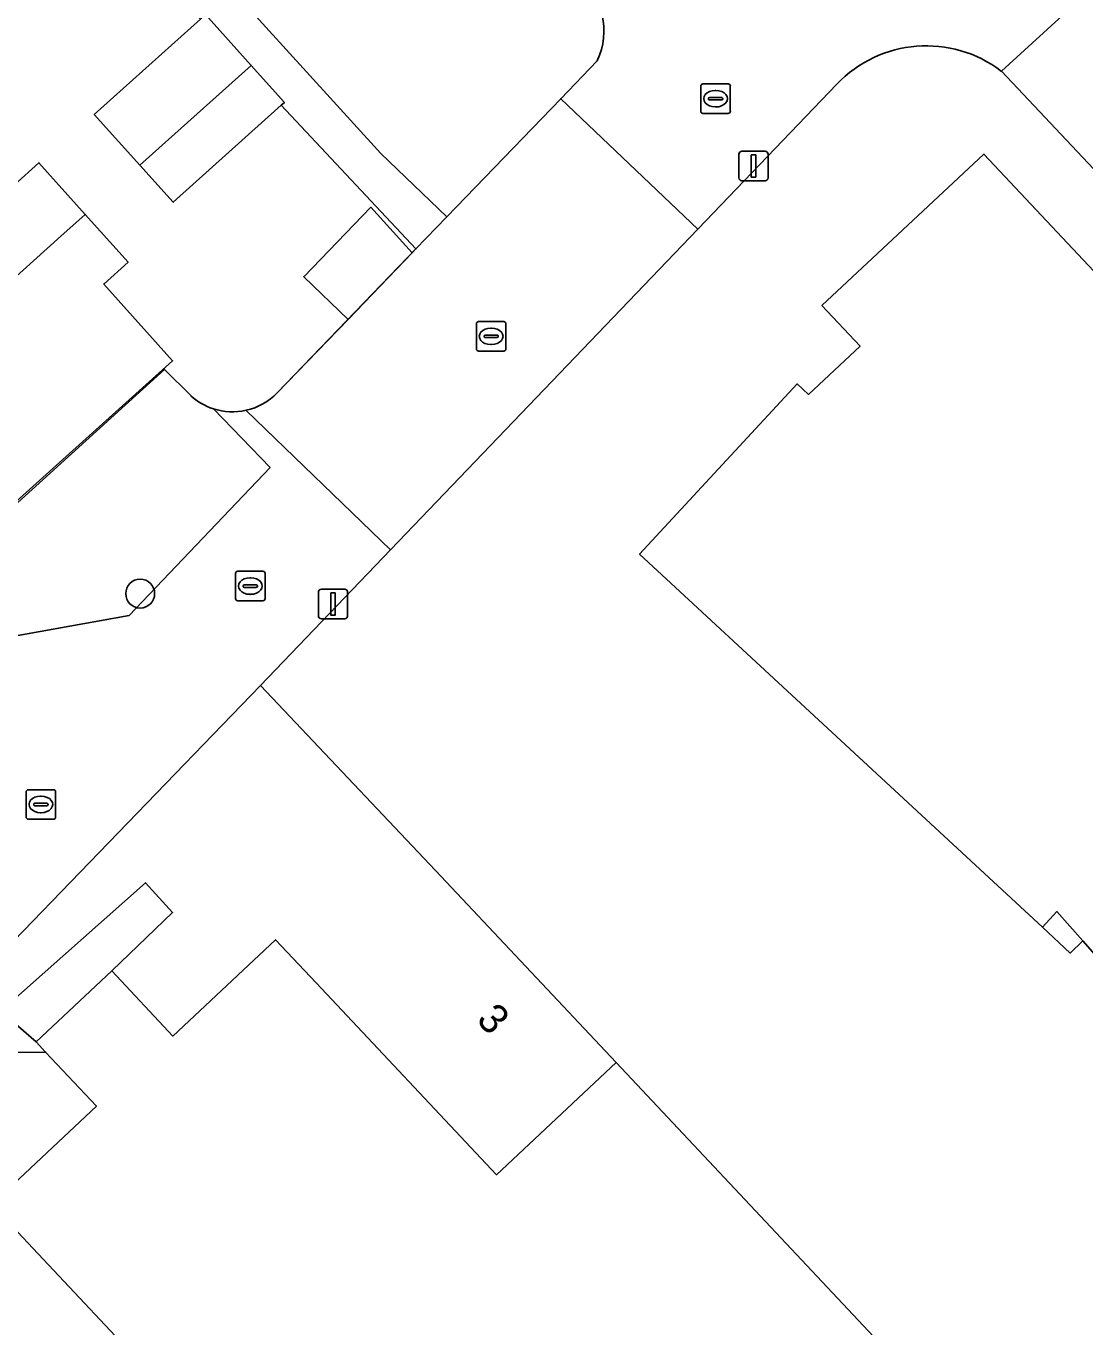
# Model space of a CAD drawing. Extents: x 162344 to 162869, y 381217 to 381818.
# Drawn here: x 162687 to 162722.83, y 381421.83 to 381465.85 of the extents above; entities that cross this region are included whole.
import ezdxf

# ---------------------------------------------------------------- set-up
doc = ezdxf.new("R2010")
doc.units = 0
for name, color, linetype in [('IMGEO_Boom', 7, 'Continuous'), ('IMGEO_Erf', 7, 'Continuous'), ('IMGEO_Kolk', 7, 'Continuous'), ('IMGEO_Lichtmast', 7, 'Continuous'), ('IMGEO_Muur', 7, 'Continuous'), ('IMGEO_Pand', 7, 'Continuous'), ('IMGEO_Pand_nummerreeks', 7, 'Continuous'), ('IMGEO_Pand_overbouw', 7, 'Continuous'), ('IMGEO_Rijbaan_lokaal_open', 7, 'Continuous'), ('IMGEO_Terreindeel_open', 7, 'Continuous'), ('IMGEO_Voetpad_open', 7, 'Continuous')]:
    doc.layers.add(name, color=color, linetype=linetype)

msp = doc.modelspace()

# ---------------------------------------------------------------- linework, layer by layer
at = {"layer": 'IMGEO_Boom'}
msp.add_circle((162690.863, 381446.627), 0.489, dxfattribs=at)
at = {"layer": 'IMGEO_Erf'}
for points in [[(162685.58, 381476.325), (162688.135, 381473.509), (162691.814, 381476.884), (162693.17, 381475.405), (162694.585, 381473.863), (162690.89, 381470.473), (162699.002, 381461.533), (162701.237, 381459.381), (162705.092, 381463.385), (162706.33, 381464.671)], [(162695.638, 381463.162), (162691.98, 381459.878), (162690.856, 381461.131), (162689.308, 381462.855), (162692.902, 381466.082), (162688.04, 381471.271), (162684.241, 381467.846)], [(162754.013, 381428.168), (162752.967, 381429.308), (162720.009, 381464.312)], [(162714.432, 381463.872), (162709.731, 381458.964), (162699.33, 381448.107), (162694.93, 381443.515), (162700.859, 381437.25), (162706.964, 381430.752), (162720.044, 381416.828), (162715.93, 381412.961), (162723.279, 381405.142), (162719.898, 381401.952), (162721.872, 381399.698), (162719.263, 381397.26), (162717.216, 381399.452), (162713.77, 381396.149), (162709.224, 381401.003), (162706.22, 381398.189), (162703.408, 381401.193), (162687.52, 381386.257), (162689.397, 381384.258)], [(162695.501, 381453.423), (162697.897, 381455.912), (162696.398, 381457.355), (162698.666, 381459.711), (162700.069, 381458.168), (162700.195, 381458.299), (162695.638, 381463.162)], [(162686.609, 381460.473), (162687.435, 381461.214), (162689.004, 381459.468), (162690.455, 381457.852), (162689.628, 381457.109), (162691.96, 381454.512), (162685.525, 381448.735)], [(162683.206, 381446.525), (162691.689, 381454.221), (162692.575, 381453.33)], [(162690.103, 381415.319), (162687.343, 381418.257), (162690.379, 381421.109), (162685.836, 381425.945), (162689.381, 381429.276), (162687.662, 381431.106), (162683.091, 381431.065), (162681.901, 381430.17), (162662.676, 381410.063), (162654.072, 381401.064), (162653.457, 381400.36)]]:
    msp.add_lwpolyline(points, dxfattribs=at)
msp.add_lwpolyline([(162707.761, 381447.96), (162713.091, 381453.729), (162713.48, 381453.373), (162715.221, 381455.005), (162713.929, 381456.387), (162719.413, 381461.511), (162750.55, 381428.359), (162744.956, 381423.125), (162744.66, 381423.433), (162743.338, 381422.213), (162743.645, 381421.881), (162738.243, 381417.16), (162722.757, 381434.865), (162721.886, 381435.861), (162721.396, 381435.328)], close=True, dxfattribs=at)
for centre, radius, start, end in [((162704.186, 381465.683), 2.371, 334.7302, 51.2795), ((162717.465, 381460.997), 4.179, 52.4897, 136.5324), ((162693.985, 381454.898), 2.115, 282.5437, 315.7953), ((162693.992, 381454.891), 2.108, 227.7797, 252.0242), ((162693.99, 381454.892), 2.108, 252.0668, 282.4312)]:
    msp.add_arc(centre, radius, start, end, dxfattribs=at)
at = {"layer": 'IMGEO_Kolk'}
for p, q in [((162709.831, 381462.96), (162709.831, 381463.812)), ((162709.906, 381463.886), (162710.758, 381463.886)), ((162710.319, 381463.666), (162710.344, 381463.666)), ((162710.832, 381463.812), (162710.832, 381462.96)), ((162710.09, 381463.38), (162710.09, 381463.392)), ((162710.528, 381463.343), (162710.13, 381463.343)), ((162710.133, 381463.429), (162710.531, 381463.429)), ((162710.342, 381463.106), (162710.317, 381463.106)), ((162710.574, 381463.392), (162710.574, 381463.38)), ((162710.758, 381462.886), (162709.906, 381462.886)), ((162702.238, 381454.913), (162702.238, 381455.765)), ((162702.313, 381455.839), (162703.165, 381455.839)), ((162702.726, 381455.619), (162702.751, 381455.619)), ((162703.239, 381455.765), (162703.239, 381454.913)), ((162702.497, 381455.333), (162702.497, 381455.345)), ((162702.935, 381455.296), (162702.537, 381455.296)), ((162702.54, 381455.382), (162702.938, 381455.382)), ((162702.981, 381455.345), (162702.981, 381455.333)), ((162703.165, 381454.839), (162702.313, 381454.839)), ((162702.749, 381455.059), (162702.724, 381455.059)), ((162694.09, 381446.457), (162694.09, 381447.309)), ((162694.165, 381447.383), (162695.017, 381447.383)), ((162695.091, 381447.309), (162695.091, 381446.457)), ((162694.349, 381446.877), (162694.349, 381446.889)), ((162694.787, 381446.84), (162694.389, 381446.84)), ((162694.392, 381446.926), (162694.79, 381446.926)), ((162694.578, 381447.163), (162694.603, 381447.163)), ((162694.833, 381446.889), (162694.833, 381446.877)), ((162695.017, 381446.383), (162694.165, 381446.383)), ((162694.601, 381446.603), (162694.576, 381446.603)), ((162687.001, 381439.062), (162687.001, 381439.914)), ((162687.076, 381439.988), (162687.928, 381439.988)), ((162687.489, 381439.768), (162687.514, 381439.768)), ((162688.002, 381439.914), (162688.002, 381439.062)), ((162687.26, 381439.482), (162687.26, 381439.494)), ((162687.698, 381439.445), (162687.3, 381439.445)), ((162687.303, 381439.531), (162687.701, 381439.531)), ((162687.744, 381439.494), (162687.744, 381439.482)), ((162687.928, 381438.988), (162687.076, 381438.988)), ((162687.512, 381439.208), (162687.487, 381439.208))]:
    msp.add_line(p, q, dxfattribs=at)
for points in [[(162709.831, 381462.96), (162709.831, 381463.812)], [(162709.906, 381463.886), (162710.758, 381463.886)], [(162710.832, 381463.812), (162710.832, 381462.96)], [(162710.758, 381462.886), (162709.906, 381462.886)], [(162702.238, 381454.913), (162702.238, 381455.765)], [(162702.313, 381455.839), (162703.165, 381455.839)], [(162703.239, 381455.765), (162703.239, 381454.913)], [(162703.165, 381454.839), (162702.313, 381454.839)], [(162694.09, 381446.457), (162694.09, 381447.309)], [(162694.165, 381447.383), (162695.017, 381447.383)], [(162695.091, 381447.309), (162695.091, 381446.457)], [(162695.017, 381446.383), (162694.165, 381446.383)], [(162687.001, 381439.062), (162687.001, 381439.914)], [(162687.076, 381439.988), (162687.928, 381439.988)], [(162688.002, 381439.914), (162688.002, 381439.062)], [(162687.928, 381438.988), (162687.076, 381438.988)]]:
    msp.add_lwpolyline(points, dxfattribs=at)
for centre, radius, start, end in [((162709.908, 381463.81), 0.0765, 91.552, 178.448), ((162709.908, 381463.81), 0.0765, 91.552, 178.448), ((162710.756, 381463.81), 0.0765, 1.552, 88.448), ((162710.756, 381463.81), 0.0765, 1.552, 88.448), ((162710.13, 381463.389), 0.0403, 85.8775, 175.7526), ((162710.127, 381463.379), 0.0366, 178.938, 274.7102), ((162710.531, 381463.386), 0.043, 264.8664, 352.4533), ((162710.535, 381463.391), 0.0386, 1.7309, 96.639), ((162709.908, 381462.962), 0.0765, 181.552, 268.448), ((162709.908, 381462.962), 0.0765, 181.552, 268.448), ((162710.756, 381462.962), 0.0765, 271.552, 358.448), ((162710.756, 381462.962), 0.0765, 271.552, 358.448), ((162702.315, 381455.763), 0.0765, 91.552, 178.448), ((162702.315, 381455.763), 0.0765, 91.552, 178.448), ((162703.163, 381455.763), 0.0765, 1.552, 88.448), ((162703.163, 381455.763), 0.0765, 1.552, 88.448), ((162702.537, 381455.342), 0.0403, 85.8775, 175.7526), ((162702.534, 381455.332), 0.0366, 178.938, 274.7102), ((162702.938, 381455.339), 0.043, 264.8664, 352.4533), ((162702.942, 381455.344), 0.0386, 1.7309, 96.639), ((162702.315, 381454.915), 0.0765, 181.552, 268.448), ((162702.315, 381454.915), 0.0765, 181.552, 268.448), ((162703.163, 381454.915), 0.0765, 271.552, 358.448), ((162703.163, 381454.915), 0.0765, 271.552, 358.448), ((162694.167, 381447.307), 0.0765, 91.552, 178.448), ((162694.167, 381447.307), 0.0765, 91.552, 178.448), ((162695.015, 381447.307), 0.0765, 1.552, 88.448), ((162695.015, 381447.307), 0.0765, 1.552, 88.448), ((162694.389, 381446.886), 0.0403, 85.8775, 175.7526), ((162694.386, 381446.876), 0.0366, 178.938, 274.7102), ((162694.79, 381446.883), 0.043, 264.8664, 352.4533), ((162694.794, 381446.888), 0.0386, 1.7309, 96.639), ((162694.167, 381446.459), 0.0765, 181.552, 268.448), ((162694.167, 381446.459), 0.0765, 181.552, 268.448), ((162695.015, 381446.459), 0.0765, 271.552, 358.448), ((162695.015, 381446.459), 0.0765, 271.552, 358.448), ((162687.078, 381439.912), 0.0765, 91.552, 178.448), ((162687.078, 381439.912), 0.0765, 91.552, 178.448), ((162687.926, 381439.912), 0.0765, 1.552, 88.448), ((162687.926, 381439.912), 0.0765, 1.552, 88.448), ((162687.3, 381439.491), 0.0403, 85.8775, 175.7526), ((162687.297, 381439.481), 0.0366, 178.938, 274.7102), ((162687.701, 381439.488), 0.043, 264.8664, 352.4533), ((162687.705, 381439.493), 0.0386, 1.7309, 96.639), ((162687.078, 381439.064), 0.0765, 181.552, 268.448), ((162687.078, 381439.064), 0.0765, 181.552, 268.448), ((162687.926, 381439.064), 0.0765, 271.552, 358.448), ((162687.926, 381439.064), 0.0765, 271.552, 358.448)]:
    msp.add_arc(centre, radius, start, end, dxfattribs=at)
for centre, major_axis, ratio, start_param, end_param in [((162710.318, 381463.386), (-0.387, 0.002), 0.722429, 4.712389, 7.853982), ((162710.343, 381463.386), (-0.39, 0.002), 0.717154, 1.570796, 4.712389), ((162702.725, 381455.339), (-0.387, 0.002), 0.722429, 4.712389, 7.853982), ((162702.75, 381455.339), (-0.39, 0.002), 0.717154, 1.570796, 4.712389), ((162694.577, 381446.883), (-0.387, 0.002), 0.722429, 4.712389, 7.853982), ((162694.602, 381446.883), (-0.39, 0.002), 0.717154, 1.570796, 4.712389), ((162687.488, 381439.488), (-0.387, 0.002), 0.722429, 4.712389, 7.853982), ((162687.513, 381439.488), (-0.39, 0.002), 0.717154, 1.570796, 4.712389)]:
    msp.add_ellipse(centre, major_axis=major_axis, ratio=ratio, start_param=start_param, end_param=end_param, dxfattribs=at)
at = {"layer": 'IMGEO_Lichtmast'}
for p, q in [((162711.121, 381460.705), (162711.121, 381461.505)), ((162711.121, 381461.505), (162711.121, 381460.705)), ((162711.221, 381461.605), (162712.011, 381461.605)), ((162712.011, 381461.605), (162711.221, 381461.605)), ((162712.111, 381461.505), (162712.111, 381460.705)), ((162712.111, 381460.705), (162712.111, 381461.505)), ((162712.011, 381460.605), (162711.221, 381460.605)), ((162711.221, 381460.605), (162712.011, 381460.605)), ((162696.893, 381445.876), (162696.893, 381446.676)), ((162696.893, 381446.676), (162696.893, 381445.876)), ((162696.993, 381446.776), (162697.783, 381446.776)), ((162697.783, 381446.776), (162696.993, 381446.776)), ((162697.883, 381446.676), (162697.883, 381445.876)), ((162697.883, 381445.876), (162697.883, 381446.676)), ((162697.783, 381445.776), (162696.993, 381445.776)), ((162696.993, 381445.776), (162697.783, 381445.776))]:
    msp.add_line(p, q, dxfattribs=at)
for points in [[(162711.541, 381461.48), (162711.691, 381461.48), (162711.691, 381460.73), (162711.541, 381460.73), (162711.541, 381461.48)], [(162697.313, 381446.651), (162697.463, 381446.651), (162697.463, 381445.901), (162697.313, 381445.901), (162697.313, 381446.651)]]:
    msp.add_lwpolyline(points, dxfattribs=at)
for centre, start, end in [((162711.221, 381461.505), 90, 180), ((162711.221, 381461.505), 90, 180), ((162712.011, 381461.505), 0, 90), ((162712.011, 381461.505), 360, 90), ((162711.221, 381460.705), 180, 270), ((162711.221, 381460.705), 180, 270), ((162712.011, 381460.705), 270, 0), ((162712.011, 381460.705), 270, 0), ((162696.993, 381446.676), 90, 180), ((162696.993, 381446.676), 90, 180), ((162697.783, 381446.676), 0, 90), ((162697.783, 381446.676), 360, 90), ((162696.993, 381445.876), 180, 270), ((162696.993, 381445.876), 180, 270), ((162697.783, 381445.876), 270, 0), ((162697.783, 381445.876), 270, 0)]:
    msp.add_arc(centre, 0.1, start, end, dxfattribs=at)
at = {"layer": 'IMGEO_Muur'}
for points in [[(162701.237, 381459.381), (162700.195, 381458.299)], [(162700.195, 381458.299), (162695.501, 381453.423)], [(162692.575, 381453.33), (162691.689, 381454.221)]]:
    msp.add_lwpolyline(points, dxfattribs=at)
for centre, radius, start, end in [((162693.985, 381454.898), 2.115, 282.5437, 315.7953), ((162693.992, 381454.891), 2.108, 227.7797, 252.0242), ((162693.99, 381454.892), 2.108, 252.0668, 282.4312)]:
    msp.add_arc(centre, radius, start, end, dxfattribs=at)
at = {"layer": 'IMGEO_Pand'}
for points in [[(162694.62, 381464.512), (162693.073, 381466.235), (162692.902, 381466.082), (162689.308, 381462.855), (162690.856, 381461.131)], [(162695.638, 381463.162), (162695.745, 381463.258), (162694.62, 381464.512), (162690.856, 381461.131), (162691.98, 381459.878)], [(162686.009, 381457.644), (162686.44, 381457.165), (162688.178, 381458.726), (162689.004, 381459.468), (162687.435, 381461.214), (162686.609, 381460.473), (162684.245, 381463.106), (162677.81, 381457.329), (162682.063, 381452.592), (162684.691, 381454.952), (162683.94, 381455.787)], [(162713.929, 381456.387), (162715.221, 381455.005), (162713.48, 381453.373), (162713.091, 381453.729), (162707.761, 381447.96), (162721.396, 381435.328), (162721.886, 381435.861), (162722.757, 381434.865), (162738.243, 381417.16), (162743.645, 381421.881), (162743.338, 381422.213), (162744.66, 381423.433), (162744.956, 381423.125), (162750.55, 381428.359), (162719.413, 381461.511)], [(162700.069, 381458.168), (162698.666, 381459.711), (162696.398, 381457.355), (162697.897, 381455.912)], [(162689.628, 381457.109), (162690.455, 381457.852), (162689.004, 381459.468), (162688.178, 381458.726), (162686.44, 381457.165), (162686.009, 381457.644), (162683.94, 381455.787), (162684.691, 381454.952), (162682.063, 381452.592), (162685.525, 381448.735), (162691.96, 381454.512)]]:
    msp.add_lwpolyline(points, close=True, dxfattribs=at)
msp.add_lwpolyline([(162715.93, 381412.961), (162720.044, 381416.828), (162706.964, 381430.752), (162702.923, 381426.952), (162696.813, 381433.45), (162695.443, 381434.907), (162691.971, 381431.646), (162689.898, 381433.853), (162687.339, 381431.45), (162687.662, 381431.106), (162689.381, 381429.276), (162685.836, 381425.945), (162690.379, 381421.109), (162687.343, 381418.257), (162690.103, 381415.319), (162674.389, 381400.557), (162672.5, 381402.517)], dxfattribs=at)
at = {"layer": 'IMGEO_Pand_overbouw'}
msp.add_lwpolyline([(162722.757, 381434.865), (162721.886, 381435.861), (162721.396, 381435.328), (162722.336, 381434.457)], close=True, dxfattribs=at)
at = {"layer": 'IMGEO_Rijbaan_lokaal_open'}
for points in [[(162720.009, 381464.312), (162722.465, 381466.568), (162713.011, 381476.986)], [(162706.33, 381464.671), (162705.092, 381463.385), (162709.731, 381458.964), (162714.432, 381463.872)], [(162709.731, 381458.964), (162705.092, 381463.385), (162701.237, 381459.381), (162700.195, 381458.299), (162700.069, 381458.168), (162697.897, 381455.912), (162695.501, 381453.423)], [(162694.444, 381452.833), (162699.33, 381448.107), (162709.731, 381458.964)], [(162680.109, 381437.066), (162680.664, 381436.556), (162682.379, 381434.977), (162683.055, 381435.713), (162685.295, 381433.537), (162694.93, 381443.515), (162699.33, 381448.107), (162694.444, 381452.833)], [(162693.341, 381452.886), (162695.256, 381450.903), (162690.488, 381445.883), (162684.45, 381444.808), (162680.145, 381444.041)]]:
    msp.add_lwpolyline(points, dxfattribs=at)
for centre, radius, start, end in [((162704.186, 381465.683), 2.371, 334.7302, 51.2795), ((162717.465, 381460.997), 4.179, 52.4897, 136.5324), ((162693.985, 381454.898), 2.115, 282.5437, 315.7953), ((162693.99, 381454.892), 2.108, 252.0668, 282.4312)]:
    msp.add_arc(centre, radius, start, end, dxfattribs=at)
at = {"layer": 'IMGEO_Terreindeel_open'}
msp.add_lwpolyline([(162689.898, 381433.853), (162691.959, 381435.825), (162691.039, 381436.835), (162686.152, 381432.488), (162687.339, 381431.45)], close=True, dxfattribs=at)
at = {"layer": 'IMGEO_Voetpad_open'}
for points in [[(162686.611, 381472.919), (162688.106, 381471.33), (162688.04, 381471.271), (162692.902, 381466.082), (162693.073, 381466.235), (162694.62, 381464.512), (162695.745, 381463.258), (162695.638, 381463.162), (162700.195, 381458.299), (162701.237, 381459.381), (162699.002, 381461.533), (162690.89, 381470.473), (162690.801, 381470.392), (162689.426, 381471.892), (162688.03, 381473.413), (162688.135, 381473.509), (162685.58, 381476.325)], [(162737.586, 381452.376), (162736.333, 381453.714), (162731.339, 381452.54), (162730.766, 381454.796), (162729.511, 381454.534), (162728.837, 381456.828), (162727.594, 381456.566), (162727.034, 381458.822), (162725.728, 381458.662), (162725.207, 381460.778), (162728.3, 381461.547), (162728.666, 381461.803), (162728.576, 381462.553), (162723.627, 381467.636), (162722.465, 381466.568), (162720.009, 381464.312), (162752.967, 381429.308), (162754.013, 381428.168)], [(162692.575, 381453.33), (162691.689, 381454.221), (162683.206, 381446.525)], [(162679.513, 381444.074), (162679.621, 381443.954), (162680.145, 381444.041), (162684.45, 381444.808), (162690.488, 381445.883), (162695.256, 381450.903), (162693.341, 381452.886)], [(162681.901, 381430.17), (162683.091, 381431.065), (162687.662, 381431.106), (162687.339, 381431.45), (162686.152, 381432.488), (162691.039, 381436.835), (162691.959, 381435.825), (162689.898, 381433.853), (162691.971, 381431.646), (162695.443, 381434.907), (162696.813, 381433.45), (162702.923, 381426.952), (162706.964, 381430.752), (162700.859, 381437.25), (162694.93, 381443.515), (162685.295, 381433.537), (162683.055, 381435.713), (162682.379, 381434.977), (162683.023, 381432.097), (162680.632, 381431.561), (162679.317, 381436.302), (162680.664, 381436.556), (162680.109, 381437.066), (162679.729, 381437.415)]]:
    msp.add_lwpolyline(points, dxfattribs=at)
msp.add_arc((162693.992, 381454.891), 2.108, 227.7797, 252.0242, dxfattribs=at)

# ---------------------------------------------------------------- texts
at = {"layer": 'IMGEO_Pand_nummerreeks'}
msp.add_text('3', height=1, rotation=313.2123, dxfattribs=at).set_placement((162702.204, 381432.167))

doc.saveas('drawing.dxf')
